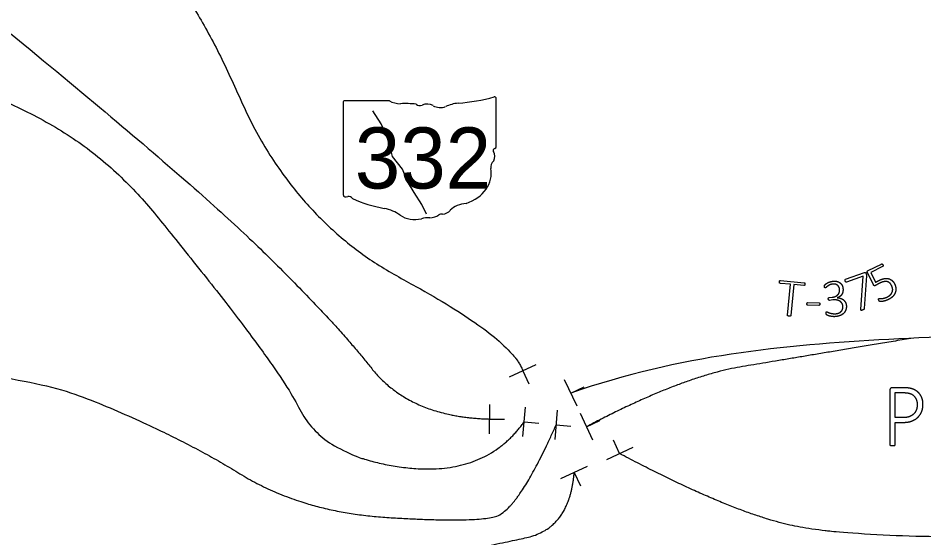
# Model space of a CAD drawing. Extents: x -740 to 1519, y 0 to 440.
# Drawn here: x 122.3 to 233.4, y 312.4 to 376.2 of the extents above; entities that cross this region are included whole.
import ezdxf

# ---------------------------------------------------------------- set-up
doc = ezdxf.new("R2010")
doc.units = 0
for name, color, linetype in [('Default', 7, 'Continuous'), ('GM_X_County_Road_Text', 7, 'Continuous'), ('GM_X_Minor_River', 7, 'Continuous'), ('GM_X_State_Location', 7, 'Continuous'), ('GM_X_Township_Road_Text', 7, 'Continuous'), ('GM_X_Township_Text', 7, 'Continuous'), ('SH_Data', 7, 'Continuous')]:
    doc.layers.add(name, color=color, linetype=linetype)

msp = doc.modelspace()

# ---------------------------------------------------------------- linework, layer by layer
at = {"layer": 'Default'}
msp.add_open_spline([(231.84, 336.89), (218.4, 334.64), (203.67, 332.18), (192.04, 326.05)], degree=2, dxfattribs=at)
at = {"layer": 'GM_X_County_Road_Text'}
for p, q in [((162.19, 365.87), (162.19, 354.48)), ((167.87, 366.06), (162.37, 366.06)), ((180.94, 360.39), (180.94, 366.35)), ((180.94, 360.39), (180.94, 360.39))]:
    msp.add_line(p, q, dxfattribs=at)
for centre, major_axis, start_param, end_param in [((162.4, 365.89), (0.217, 0), 1.712693, 3.28349), ((169.17, 367.39), (2.11, 0), 4.042523, 4.731795), ((169.87, 359.67), (7.56, 0), 1.404758, 1.657858), ((176.8, 362.59), (4, 0), 1.699011, 2.107814), ((174.26, 381.58), (19.88, 0), 4.814394, 5.042369), ((180.73, 366.37), (0.209, 0), 6.141152, 7.989035), ((171.59, 365.95), (0.608, 0), 3.836095, 5.185415), ((172.48, 364.64), (1.26, 0), 0.950623, 2.079405), ((174.11, 366.44), (1.52, 0), 4.081561, 5.145723), ((180.89, 359.95), (0.323, 0), 1.883978, 3.671073), ((180.72, 360.37), (0.223, 0), 5.05454, 6.418171), ((178.84, 359.2), (1.94, 0), 5.934695, 6.695948), ((181.69, 357.9), (1.41, 0), 2.387724, 3.262537), ((175.37, 357.14), (4.97, 0), 5.101752, 6.440018), ((162.41, 354.46), (0.219, 0), 3.00124, 4.508301), ((162.44, 355.62), (1.67, 0), 4.665946, 4.897461), ((162.78, 353.83), (0.603, 0), 0.519207, 1.627899), ((170.4, 364.05), (14.36, 0), 4.195997, 4.488961), ((166.11, 349.37), (4.49, 0), 0.823519, 1.323587), ((174.02, 353.38), (1.61, 0), 4.937069, 5.64225), ((177.47, 351.29), (2.72, 0), 1.647645, 2.488434), ((170.97, 353.77), (2.85, 0), 4.026481, 4.996735), ((172.62, 349.83), (2.34, 0), 1.495662, 1.94098), ((172.83, 352.92), (1.52, 0), 4.691044, 5.507374), ((174.2, 351.81), (0.428, 0), 1.147584, 2.315152)]:
    msp.add_ellipse(centre, major_axis=major_axis, ratio=0.8, start_param=start_param, end_param=end_param, dxfattribs=at)
at = {"layer": 'GM_X_Minor_River'}
for p, q in [((182.58, 332.17), (185.84, 333.69)), ((184.21, 332.93), (184.97, 331.3)), ((190.87, 328.56), (189.34, 331.82)), ((190.1, 330.19), (191.74, 330.95)), ((180.14, 325.2), (180.19, 328.8)), ((184.22, 324.85), (184.53, 328.44)), ((188.17, 324.5), (188.48, 328.09)), ((180.17, 327), (181.97, 326.97)), ((192.8, 324.42), (191.28, 327.68)), ((192.04, 326.05), (193.67, 326.81)), ((184.38, 326.65), (186.17, 326.49)), ((188.32, 326.29), (190.12, 326.14)), ((197.74, 323.52), (194.47, 321.99)), ((196.1, 322.76), (195.34, 324.39)), ((188.9, 319.68), (192.16, 321.21)), ((190.53, 320.44), (191.29, 318.81))]:
    msp.add_line(p, q, dxfattribs=at)
at = {"layer": 'GM_X_State_Location'}
for p, q in [((229.26, 330.49), (229.26, 323.87)), ((231, 330.84), (229.57, 330.84)), ((232.62, 328.75), (232.62, 328.75)), ((233.33, 328.81), (233.33, 328.81))]:
    msp.add_line(p, q, dxfattribs=at)
for points in [[(230.89, 327.17), (229.93, 327.17), (229.93, 330.24), (230.93, 330.24)], [(229.93, 323.87), (229.93, 326.58), (230.85, 326.58)]]:
    msp.add_lwpolyline(points, dxfattribs=at)
for points in [[(229.36, 330.76), (229.26, 330.69), (229.26, 330.49)], [(229.57, 330.84), (229.47, 330.84), (229.36, 330.76)], [(230.93, 330.24), (231.18, 330.24), (231.46, 330.2)], [(231.42, 330.82), (231.22, 330.84), (231, 330.84)], [(231.89, 330.74), (231.62, 330.8), (231.42, 330.82)], [(231.46, 330.2), (231.75, 330.16), (232.01, 330.01)], [(232.44, 330.5), (232.16, 330.67), (231.89, 330.74)], [(232.92, 330.08), (232.73, 330.33), (232.44, 330.5)], [(232.01, 330.01), (232.26, 329.85), (232.44, 329.53)], [(232.44, 329.53), (232.62, 329.21), (232.62, 328.75)], [(233.23, 329.51), (233.12, 329.83), (232.92, 330.08)], [(233.33, 328.81), (233.33, 329.19), (233.23, 329.51)], [(232.51, 328.12), (232.4, 327.82), (232.19, 327.62)], [(232.62, 328.75), (232.62, 328.41), (232.51, 328.12)], [(233.17, 327.91), (233.33, 328.32), (233.33, 328.81)], [(231.66, 327.29), (231.35, 327.17), (230.89, 327.17)], [(232.19, 327.62), (231.98, 327.41), (231.66, 327.29)], [(231.93, 326.74), (232.38, 326.91), (232.69, 327.2)], [(232.69, 327.2), (233, 327.5), (233.17, 327.91)], [(230.85, 326.58), (231.48, 326.58), (231.93, 326.74)], [(229.26, 323.87), (229.26, 323.84), (229.28, 323.81)], [(229.28, 323.81), (229.29, 323.79), (229.33, 323.77)], [(229.33, 323.77), (229.37, 323.75), (229.44, 323.74)], [(229.44, 323.74), (229.5, 323.73), (229.59, 323.73)], [(229.59, 323.73), (229.69, 323.73), (229.76, 323.74)], [(229.76, 323.74), (229.82, 323.75), (229.86, 323.77)], [(229.86, 323.77), (229.9, 323.79), (229.91, 323.81)], [(229.91, 323.81), (229.93, 323.84), (229.93, 323.87)]]:
    msp.add_open_spline(points, degree=2, dxfattribs=at)
at = {"layer": 'GM_X_Township_Road_Text'}
for p, q in [((166.85, 363.21), (165.8, 364.81)), ((167.46, 361.98), (166.85, 363.21)), ((167.92, 360.37), (167.46, 361.98)), ((168.23, 359.22), (167.92, 360.37)), ((169.45, 357.66), (168.23, 359.22)), ((170.08, 356.14), (169.45, 357.66)), ((170.87, 354.79), (170.08, 356.14)), ((171.83, 353.31), (170.87, 354.79)), ((172.4, 352.13), (171.83, 353.31))]:
    msp.add_line(p, q, dxfattribs=at)
at = {"layer": 'GM_X_Township_Text'}
for p, q in [((226.6, 345.22), (228.22, 346.02)), ((223.84, 344.15), (226.14, 344.97)), ((226.34, 344.85), (226.34, 344.85)), ((227.25, 343.47), (226.51, 344.97)), ((215.84, 344.01), (218.76, 343.73)), ((218.84, 343.54), (218.84, 343.54)), ((226.38, 344.56), (226.11, 340.56)), ((229.84, 343.6), (229.84, 343.6)), ((219.19, 341.29), (220.57, 341.27)), ((221.82, 341.91), (222.19, 341.95)), ((222.27, 341.61), (221.85, 341.56)), ((222.8, 341.88), (222.8, 341.88)), ((220.56, 340.95), (219.19, 340.97)), ((220.66, 341.11), (220.66, 341.11)), ((223.92, 340.97), (223.92, 340.97))]:
    msp.add_line(p, q, dxfattribs=at)
for points in [[(228.37, 345.7), (226.92, 344.99), (227.51, 343.78)], [(216.7, 339.73), (217.07, 343.53), (215.8, 343.65)], [(218.72, 343.37), (217.46, 343.49), (217.1, 339.69)], [(225.7, 340.44), (226, 344.54), (223.96, 343.81)]]:
    msp.add_lwpolyline(points, dxfattribs=at)
for points in [[(228.22, 346.02), (228.24, 346.03), (228.27, 346.03)], [(228.27, 346.03), (228.29, 346.03), (228.32, 346.02)], [(228.32, 346.02), (228.34, 346.01), (228.36, 345.98)], [(228.36, 345.98), (228.38, 345.95), (228.4, 345.92)], [(228.43, 345.79), (228.43, 345.73), (228.37, 345.7)], [(228.4, 345.92), (228.44, 345.85), (228.43, 345.79)], [(226.14, 344.97), (226.18, 344.98), (226.21, 344.98)], [(226.21, 344.98), (226.24, 344.98), (226.26, 344.97)], [(226.26, 344.97), (226.29, 344.95), (226.31, 344.92)], [(226.31, 344.92), (226.32, 344.89), (226.34, 344.85)], [(226.34, 344.85), (226.35, 344.81), (226.36, 344.78)], [(226.36, 344.78), (226.37, 344.75), (226.38, 344.71)], [(226.38, 344.71), (226.38, 344.68), (226.38, 344.64)], [(226.38, 344.64), (226.38, 344.6), (226.38, 344.56)], [(226.51, 344.97), (226.47, 345.05), (226.5, 345.12)], [(226.5, 345.12), (226.52, 345.19), (226.6, 345.22)], [(215.72, 343.84), (215.72, 343.88), (215.73, 343.91)], [(215.72, 343.76), (215.72, 343.79), (215.72, 343.84)], [(215.73, 343.7), (215.72, 343.73), (215.72, 343.76)], [(215.73, 343.91), (215.74, 343.95), (215.76, 343.97)], [(215.76, 343.67), (215.74, 343.68), (215.73, 343.7)], [(215.76, 343.97), (215.77, 343.99), (215.79, 344)], [(215.8, 343.65), (215.78, 343.66), (215.76, 343.67)], [(215.79, 344), (215.81, 344.01), (215.84, 344.01)], [(218.76, 343.73), (218.78, 343.72), (218.8, 343.71)], [(218.8, 343.71), (218.82, 343.7), (218.83, 343.67)], [(218.83, 343.67), (218.84, 343.65), (218.84, 343.62)], [(218.84, 343.54), (218.84, 343.49), (218.83, 343.46)], [(218.84, 343.62), (218.85, 343.58), (218.84, 343.54)], [(221.29, 343.47), (221.32, 343.5), (221.4, 343.57)], [(221.4, 343.57), (221.49, 343.64), (221.62, 343.71)], [(221.62, 343.71), (221.74, 343.78), (221.91, 343.84)], [(221.91, 343.84), (222.07, 343.89), (222.27, 343.91)], [(222.27, 343.56), (222.07, 343.54), (221.91, 343.47)], [(222.27, 343.91), (222.56, 343.94), (222.78, 343.89)], [(222.6, 343.54), (222.46, 343.58), (222.27, 343.56)], [(222.85, 343.41), (222.75, 343.5), (222.6, 343.54)], [(222.78, 343.89), (223, 343.83), (223.15, 343.71)], [(223.15, 343.71), (223.31, 343.59), (223.4, 343.41)], [(223.77, 344.01), (223.76, 344.04), (223.77, 344.07)], [(223.77, 344.07), (223.78, 344.1), (223.79, 344.12)], [(223.78, 343.94), (223.77, 343.98), (223.77, 344.01)], [(223.86, 343.83), (223.81, 343.87), (223.78, 343.94)], [(223.79, 344.12), (223.81, 344.14), (223.84, 344.15)], [(223.96, 343.81), (223.9, 343.79), (223.86, 343.83)], [(227.71, 343.5), (227.59, 343.42), (227.48, 343.37)], [(227.51, 343.78), (227.61, 343.84), (227.72, 343.9)], [(228.01, 343.67), (227.82, 343.58), (227.71, 343.5)], [(227.72, 343.9), (227.83, 343.96), (227.98, 344.03)], [(227.98, 344.03), (228.32, 344.2), (228.61, 344.24)], [(228.5, 343.85), (228.28, 343.8), (228.01, 343.67)], [(228.91, 343.86), (228.73, 343.9), (228.5, 343.85)], [(228.61, 344.24), (228.9, 344.28), (229.13, 344.22)], [(229.24, 343.7), (229.1, 343.83), (228.91, 343.86)], [(229.13, 344.22), (229.36, 344.15), (229.54, 343.99)], [(229.48, 343.38), (229.38, 343.58), (229.24, 343.7)], [(229.54, 343.99), (229.72, 343.83), (229.84, 343.6)], [(229.84, 343.6), (229.99, 343.3), (230, 343.01)], [(218.77, 343.38), (218.75, 343.37), (218.72, 343.37)], [(218.8, 343.41), (218.79, 343.39), (218.77, 343.38)], [(218.83, 343.46), (218.82, 343.43), (218.8, 343.41)], [(221.23, 343.32), (221.23, 343.35), (221.24, 343.37)], [(221.23, 343.25), (221.23, 343.29), (221.23, 343.32)], [(221.25, 343.17), (221.24, 343.2), (221.23, 343.25)], [(221.24, 343.37), (221.25, 343.39), (221.26, 343.42)], [(221.27, 343.11), (221.26, 343.13), (221.25, 343.17)], [(221.26, 343.42), (221.27, 343.44), (221.29, 343.47)], [(221.3, 343.09), (221.28, 343.1), (221.27, 343.11)], [(221.34, 343.09), (221.32, 343.09), (221.3, 343.09)], [(221.44, 343.16), (221.37, 343.09), (221.34, 343.09)], [(221.63, 343.31), (221.52, 343.22), (221.44, 343.16)], [(221.91, 343.47), (221.75, 343.39), (221.63, 343.31)], [(223.02, 343.2), (222.96, 343.32), (222.85, 343.41)], [(222.89, 342.26), (223.01, 342.39), (223.06, 342.56)], [(223.09, 342.93), (223.08, 343.07), (223.02, 343.2)], [(223.06, 342.56), (223.11, 342.73), (223.09, 342.93)], [(223.49, 342.62), (223.46, 342.44), (223.37, 342.3)], [(223.4, 343.41), (223.49, 343.22), (223.51, 343.01)], [(223.51, 343.01), (223.53, 342.8), (223.49, 342.62)], [(227.36, 343.35), (227.3, 343.37), (227.25, 343.47)], [(227.48, 343.37), (227.41, 343.33), (227.36, 343.35)], [(229.31, 342.22), (229.46, 342.36), (229.54, 342.54)], [(229.61, 342.92), (229.6, 343.13), (229.48, 343.38)], [(229.54, 342.54), (229.62, 342.71), (229.61, 342.92)], [(229.91, 342.48), (229.81, 342.22), (229.6, 342.01)], [(230, 343.01), (230.02, 342.73), (229.91, 342.48)], [(219.09, 341.13), (219.09, 341.22), (219.12, 341.26)], [(219.12, 341.26), (219.15, 341.29), (219.19, 341.29)], [(220.57, 341.27), (220.59, 341.27), (220.61, 341.26)], [(220.61, 341.26), (220.62, 341.26), (220.64, 341.24)], [(221.71, 341.73), (221.71, 341.77), (221.72, 341.8)], [(221.73, 341.65), (221.72, 341.68), (221.71, 341.73)], [(221.72, 341.8), (221.72, 341.83), (221.74, 341.86)], [(221.77, 341.6), (221.75, 341.62), (221.73, 341.65)], [(221.74, 341.86), (221.75, 341.88), (221.77, 341.89)], [(221.77, 341.89), (221.79, 341.9), (221.82, 341.91)], [(221.81, 341.57), (221.79, 341.58), (221.77, 341.6)], [(221.85, 341.56), (221.83, 341.56), (221.81, 341.57)], [(222.19, 341.95), (222.41, 341.97), (222.59, 342.05)], [(222.75, 341.6), (222.53, 341.64), (222.27, 341.61)], [(222.59, 342.05), (222.77, 342.13), (222.89, 342.26)], [(223.13, 341.46), (222.97, 341.56), (222.75, 341.6)], [(223.13, 342.04), (222.99, 341.94), (222.8, 341.88)], [(222.8, 341.88), (223.02, 341.88), (223.21, 341.81)], [(223.37, 342.3), (223.28, 342.15), (223.13, 342.04)], [(223.38, 341.21), (223.29, 341.36), (223.13, 341.46)], [(223.21, 341.81), (223.41, 341.75), (223.56, 341.63)], [(223.56, 341.63), (223.71, 341.51), (223.8, 341.34)], [(223.8, 341.34), (223.9, 341.17), (223.92, 340.97)], [(227.87, 341.7), (227.87, 341.73), (227.88, 341.75)], [(227.88, 341.65), (227.87, 341.68), (227.87, 341.7)], [(227.88, 341.75), (227.89, 341.76), (227.91, 341.77)], [(227.91, 341.58), (227.89, 341.61), (227.88, 341.65)], [(227.91, 341.77), (227.94, 341.79), (228.02, 341.78)], [(227.95, 341.51), (227.93, 341.54), (227.91, 341.58)], [(227.98, 341.47), (227.96, 341.49), (227.95, 341.51)], [(228.01, 341.44), (227.99, 341.45), (227.98, 341.47)], [(228.05, 341.43), (228.02, 341.43), (228.01, 341.44)], [(228.02, 341.78), (228.1, 341.77), (228.23, 341.78)], [(228.18, 341.42), (228.08, 341.42), (228.05, 341.43)], [(228.41, 341.44), (228.27, 341.42), (228.18, 341.42)], [(228.23, 341.78), (228.37, 341.79), (228.54, 341.83)], [(228.73, 341.52), (228.56, 341.47), (228.41, 341.44)], [(228.54, 341.83), (228.72, 341.87), (228.94, 341.98)], [(229.08, 341.66), (228.9, 341.57), (228.73, 341.52)], [(228.94, 341.98), (229.15, 342.08), (229.31, 342.22)], [(229.6, 342.01), (229.38, 341.81), (229.08, 341.66)], [(219.12, 341), (219.09, 341.04), (219.09, 341.13)], [(219.19, 340.97), (219.15, 340.97), (219.12, 341)], [(220.63, 340.98), (220.61, 340.94), (220.56, 340.95)], [(220.66, 341.11), (220.66, 341.01), (220.63, 340.98)], [(220.64, 341.24), (220.65, 341.22), (220.66, 341.19)], [(220.66, 341.19), (220.66, 341.15), (220.66, 341.11)], [(221.45, 340.12), (221.47, 340.16), (221.51, 340.16)], [(221.51, 340.16), (221.53, 340.16), (221.63, 340.12)], [(223.04, 340.03), (223.21, 340.11), (223.32, 340.23)], [(223.32, 340.23), (223.43, 340.36), (223.47, 340.52)], [(223.5, 340.86), (223.48, 341.06), (223.38, 341.21)], [(223.47, 340.52), (223.52, 340.68), (223.5, 340.86)], [(223.88, 340.45), (223.81, 340.22), (223.65, 340.03)], [(223.92, 340.97), (223.95, 340.69), (223.88, 340.45)], [(225.7, 340.37), (225.7, 340.4), (225.7, 340.44)], [(225.73, 340.34), (225.7, 340.35), (225.7, 340.37)], [(225.79, 340.33), (225.75, 340.32), (225.73, 340.34)], [(225.9, 340.36), (225.83, 340.33), (225.79, 340.33)], [(226, 340.4), (225.96, 340.38), (225.9, 340.36)], [(226.06, 340.44), (226.04, 340.42), (226, 340.4)], [(226.1, 340.49), (226.09, 340.46), (226.06, 340.44)], [(226.11, 340.56), (226.11, 340.52), (226.1, 340.49)], [(216.71, 339.69), (216.7, 339.71), (216.7, 339.73)], [(216.74, 339.66), (216.71, 339.68), (216.71, 339.69)], [(216.8, 339.64), (216.76, 339.65), (216.74, 339.66)], [(216.89, 339.63), (216.84, 339.63), (216.8, 339.64)], [(216.99, 339.62), (216.95, 339.62), (216.89, 339.63)], [(217.05, 339.63), (217.03, 339.63), (216.99, 339.62)], [(217.09, 339.66), (217.07, 339.64), (217.05, 339.63)], [(217.1, 339.69), (217.1, 339.67), (217.09, 339.66)], [(221.44, 339.98), (221.43, 340.08), (221.45, 340.12)], [(221.46, 339.89), (221.45, 339.93), (221.44, 339.98)], [(221.48, 339.83), (221.47, 339.86), (221.46, 339.89)], [(221.5, 339.79), (221.49, 339.81), (221.48, 339.83)], [(221.54, 339.76), (221.52, 339.77), (221.5, 339.79)], [(221.67, 339.7), (221.57, 339.74), (221.54, 339.76)], [(221.63, 340.12), (221.73, 340.07), (221.87, 340.02)], [(221.91, 339.62), (221.77, 339.65), (221.67, 339.7)], [(221.87, 340.02), (222.02, 339.97), (222.22, 339.94)], [(222.25, 339.57), (222.06, 339.59), (221.91, 339.62)], [(222.22, 339.94), (222.41, 339.9), (222.64, 339.92)], [(222.64, 339.57), (222.43, 339.55), (222.25, 339.57)], [(222.64, 339.92), (222.87, 339.95), (223.04, 340.03)], [(223.24, 339.73), (222.99, 339.61), (222.64, 339.57)], [(223.65, 340.03), (223.5, 339.85), (223.24, 339.73)]]:
    msp.add_open_spline(points, degree=2, dxfattribs=at)
at = {"layer": 'SH_Data'}
msp.add_circle((190, 328.25), 90, dxfattribs=at)
for points, degree in [([(69.4, 404.11), (82.79, 405.62), (141.27, 358.21), (160.83, 339.36), (170.35, 327.23), (180.17, 327)], 2), ([(113.24, 399.12), (114.19, 396.29), (124.55, 396.46), (142.54, 382.43), (155.9, 351.48), (182.81, 336.97), (184.21, 332.93)], 2), ([(88.84, 371.64), (123.17, 371.48), (153.86, 334.17), (159.8, 322.29), (179.52, 319.82), (184.38, 326.65)], 2), ([(292.24, 338.74), (285.13, 336.33), (269.67, 337.89), (228.49, 337.27), (203.65, 334.85), (190.1, 330.19)], 3), ([(89.43, 334.15), (119.97, 333.88), (141.84, 325.02), (157.11, 315.58), (178.04, 314.26), (183.64, 315.77), (188.32, 326.29)], 2), ([(301.11, 286.38), (297.47, 298.35), (284.27, 305.71), (265.34, 312.77), (224.97, 312.3), (209.77, 315.51), (196.1, 322.76)], 2), ([(71.68, 275.49), (71.08, 286.38), (82.97, 292.81), (119.92, 301.72), (148.58, 305.92), (179.75, 311.29), (189.97, 313.69), (190.53, 320.44)], 2)]:
    msp.add_open_spline(points, degree=degree, dxfattribs=at)

# ---------------------------------------------------------------- texts
at = {"layer": 'GM_X_County_Road_Text'}
msp.add_text('332', height=7.5, dxfattribs=at).set_placement((163.6, 355.29))

doc.saveas('drawing.dxf')
